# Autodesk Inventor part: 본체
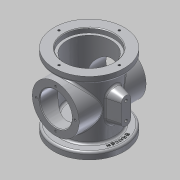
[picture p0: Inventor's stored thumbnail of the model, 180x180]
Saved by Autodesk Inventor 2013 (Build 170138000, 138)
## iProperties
Created: 2018-02
Part Number: 본체
Material: 알루미늄 6061
Document SubType Name: Modeling
Designer: Administrator
Mass: 771.854 g
Surface Area: 821.859 cm^2
Volume: 284.817 cm^3
Density: 2.71 g/cm^3
Author: Administrator
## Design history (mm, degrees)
sketch "스케치2"
  geometry: C1 r 38 at (0, 0); 1 further point
  constraints: 1 centre point, 1 coincident
  dimensions: "d0" = 76 diameter of C1
extrude "돌출1" new body sketch "스케치2" distance "d2" = 108; taper "d3" = 0 deg
sketch "스케치3"
  geometry: C1 r 38 at (0, 0) reference; C2 r 52.5 at (0, 0)
  constraints: 1 centre point, 1 coincident
  dimensions: "d4" = 105 diameter of C2
extrude "돌출2" join sketch "스케치3" distance "d6" = 10; taper "d7" = 0 deg
sketch "스케치4"
  geometry: C1 r 38 at (0, 0) reference; C2 r 52.5 at (0, 0)
  constraints: 1 centre point, 1 coincident
  dimensions: "d8" = 105 diameter of C2
extrude "돌출3" join sketch "스케치4" distance "d10" = 10; taper "d11" = 0 deg
sketch "스케치5"
  geometry: C1 r 52.5 at (0, 0) reference; C2 r 37 at (0, 0)
  constraints: 1 centre point, 1 coincident
  dimensions: "d12" = 74 diameter of C2
extrude "돌출4" cut sketch "스케치5" distance "d14" = 7; taper "d15" = 0 deg
sketch "스케치6"
  geometry: C1 r 37 at (0, 0) reference; C2 r 33 at (0, 0)
  constraints: 1 centre point, 1 coincident
  dimensions: "d16" = 66 diameter of C2
extrude "돌출5" cut sketch "스케치6" distance "d18" = 79; taper "d19" = 0 deg
sketch "스케치7"
  geometry: C1 r 33 at (0, 0) reference; C2 r 5 at (0, 0)
  constraints: 1 centre point, 1 coincident
  dimensions: "d20" = 10 diameter of C2
extrude "돌출6" cut sketch "스케치7" stored distance "d22" = 79; taper "d23" = 0 deg
sketch "스케치8"
  geometry: C1 r 5 at (0, 0) reference; C2 r 52.5 at (0, 0) reference; C3 r 34 at (0, 0)
  constraints: 2 coincident, 1 centre point
  dimensions: "d24" = 68 diameter of C3
extrude "돌출7" cut sketch "스케치8" distance "d26" = 16; taper "d27" = 0 deg
chamfer "모따기1" distance "d28" = 1; stored, may be unused: second distance "d29" = 2, angle "d30" = 45 deg
fillet "모깎기1" dims "d31" = 3
sketch "스케치9" dims "d32" = 90
  geometry: L1 (0, 0)-(0, 45); C1 r 38 at (0, 0) reference; 4 further points
  constraints: 2 coincident, 2 end point, 1 vertical, 1 vertical alignment, 7 other
  dimensions: "d36" = 360 deg dimension on L1.start point (0, 45) (derived)
hole "구멍1" sketch "스케치9" at (0, 45), (-45, 0), (0, -45), (45, 0) diameter "d38" = 3.242; stored, may be unused: countersink angle "d42" = 90 deg, drill point angle "d44" = 118 deg; dims "d39" = 4, "d40" = 4, "d41" = 2, "d43" = 6
node "작업 평면1"
sketch "스케치10"
  geometry: L1 (52.5, 0)-(-52.5, 0) reference; C1 r 35 at (0, 54); 2 further points
  constraints: 1 centre point, 1 midpoint, 1 vertical alignment
  dimensions: "d46" = 70 diameter of C1; "d48" = 54 distance from line of L1 C1.centre
extrude "돌출8" join sketch "스케치10" stored distance "d49" = 16; taper "d50" = 0 deg
node "작업 평면2"
sketch "스케치11"
  geometry: L1 (52.5, 0)-(-52.5, 0) reference; C1 r 35 at (0, 54); 1 further point
  constraints: 1 centre point, 1 vertical alignment
  dimensions: "d52" = 70 diameter of C1; "d54" = 54 distance from line of L1 C1.centre
extrude "돌출9" join sketch "스케치11" stored distance "d55" = 16; taper "d56" = 0 deg
sketch "스케치12"
  geometry: C1 r 35 at (0, 0) reference; C2 r 24 at (0, 0); 1 further point
  constraints: 1 centre point, 1 coincident
  dimensions: "d57" = 48 diameter of C2
extrude "돌출10" cut sketch "스케치12" stored distance "d59" = 16; taper "d60" = 0 deg
chamfer "모따기2" distance "d61" = 1; stored, may be unused: second distance "d62" = 2, angle "d63" = 45 deg
sketch "스케치13" dims "d64" = 58
  geometry: L1 (0, 0)-(0, 29); C1 r 25 at (0, 0) reference; 5 further points
  constraints: 2 coincident, 2 end point, 1 vertical, 1 vertical alignment, 7 other
  dimensions: "d68" = 360 deg dimension on L1.start point (0, 29) (derived)
hole "구멍2" sketch "스케치13" at (0, 29), (-29, 0), (0, -29), (29, 0) diameter "d70" = 3.242; stored, may be unused: countersink angle "d74" = 90 deg, drill point angle "d76" = 118 deg; dims "d71" = 4, "d72" = 4, "d73" = 2, "d75" = 6
sketch "스케치14" dims "d77" = 58
  geometry: L1 (0, 0)-(0, 29); C1 r 25 at (0, 0) reference; 5 further points
  constraints: 2 coincident, 2 end point, 1 vertical, 1 vertical alignment, 7 other
  dimensions: "d81" = 360 deg dimension on L1.start point (0, 29) (derived)
hole "구멍3" sketch "스케치14" at (0, 29), (-29, 0), (0, -29), (29, 0) diameter "d83" = 3.242; stored, may be unused: countersink angle "d87" = 90 deg, drill point angle "d89" = 118 deg; dims "d84" = 4, "d85" = 4, "d86" = 2, "d88" = 6
fillet "모깎기2" dims "d90" = 3
node "작업 평면3"
sketch "스케치15"
  geometry: L1 (52.5, 0)-(-52.5, 0) reference; L2 (7, 67)-(7, 41); L3 (-7, 67)-(-7, 41); A1 r 7 centre (0, 67) between (7, 67) and (-7, 67); A2 r 7 centre (0, 41) between (-7, 41) and (7, 41); 1 further point
  constraints: 4 end point, 4 point on circle, 3 tangent, 2 centre point, 2 vertical alignment, 1 equal radius, 1 perpendicular
  dimensions: "d92" = 14 diameter of A1; "d94" = 40 dimension on A2 A1; "d95" = 41 distance from line of L1 A2.centre
extrude "돌출11" join sketch "스케치15" stored distance "d96" = 16; taper "d97" = 15 deg
fillet "모깎기3" dims "d98" = 3
sketch "스케치16"
  geometry: A1 r 7 centre (-67, 0) between (-67, 7) and (-67, -7) reference; A2 r 7 centre (-41, 0) between (-41, -7) and (-41, 7) reference; 1 further point
hole "구멍4" sketch "스케치16" at (-67, 0), (-41, 0) diameter "d99" = 4.134; stored, may be unused: countersink angle "d103" = 90 deg, drill point angle "d105" = 118 deg; dims "d100" = 6, "d101" = 4, "d102" = 2, "d104" = 8
sketch "스케치17"
  geometry: C1 r 49.5 at (0, 0) reference; C2 r 43 at (0, 0)
  constraints: 1 centre point, 1 coincident, 1 other
  dimensions: "d106" = 86 diameter of C2
extrude "돌출12" join sketch "스케치17" distance "d108" = 0.5; taper "d109" = 0 deg
node "솔리드1"
other parameters: "d91" = 55
